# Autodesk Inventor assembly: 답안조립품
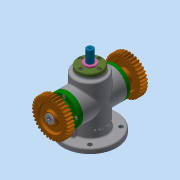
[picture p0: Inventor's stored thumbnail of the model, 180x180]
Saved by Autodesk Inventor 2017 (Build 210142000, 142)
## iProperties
Part Number: 답안조립품
Material: 일반
Document SubType Name: Assembly
Designer: mrc
Author: mrc
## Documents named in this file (17)
- C:\Users\mrc\Desktop\600606V1010\답안조립품.iam
- C:\Users\mrc\Desktop\600606V1010\본체.ipt
- C:\Users\mrc\Desktop\600606V1010\Ű 4x4x12.ipt
- C:\Users\mrc\Desktop\600606V1010\가변스프링.ipt
- C:\Users\mrc\Desktop\600606V1010\멈춤링.ipt
- C:\Users\mrc\Desktop\600606V1010\베어링 6203.ipt
- C:\Users\mrc\Desktop\600606V1010\볼트 M4.ipt
- C:\Users\mrc\Desktop\600606V1010\부시.ipt
- C:\Users\mrc\Desktop\600606V1010\스퍼기어.ipt
- C:\Users\mrc\Desktop\600606V1010\스프링와셔.ipt
- C:\Users\mrc\Desktop\600606V1010\스프링조립용 와셔.ipt
- C:\Users\mrc\Desktop\600606V1010\슬라이더.ipt
- C:\Users\mrc\Desktop\600606V1010\오일 실 17 30 8.ipt
- C:\Users\mrc\Desktop\600606V1010\커버 A.ipt
- C:\Users\mrc\Desktop\600606V1010\커버 B.ipt
- C:\Users\mrc\Desktop\600606V1010\편심축.ipt
- C:\Users\mrc\Desktop\600606V1010\평와셔.ipt
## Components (3 placed, 2 different names)
1. Ű 4x4x12:1
2. 가변스프링:1
3. Ű 4x4x12:2
